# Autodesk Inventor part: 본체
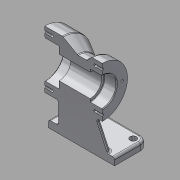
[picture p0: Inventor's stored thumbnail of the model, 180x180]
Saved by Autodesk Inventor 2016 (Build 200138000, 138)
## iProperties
Created: 2019-01
Part Number: 본체
Material: 알루미늄 6061
Document SubType Name: Modeling
Designer: MIRAE
Density: 2.7 g/cm^3
Appearance: 알루미늄 - 평지
Mass: 898.935 g
Surface Area: 600.974 cm^2
Volume: 332.939 cm^3
Author: MIRAE
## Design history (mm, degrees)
sketch "스케치1"
  geometry: L1 (-80, 0)-(0, 0); L2 (0, 0)-(0, 40); L3 (0, 40)-(-25, 40); L4 (-25, 40)-(-45.785, 28); L5 (-45.785, 28)-(-59.126, 28); L6 (-65, 35)-(-80, 35); L7 (-80, 35)-(-80, 0); L8 (-59.126, 28)-(-65, 35); 2 further points
  constraints: 16 end point, 2 parallel, 2 perpendicular, 1 coincident, 1 horizontal, 1 midpoint, 1 vertical
  dimensions: "d0" = 80 diameter of L3 L1; "d1" = 70 diameter of L6 L1; "d2" = 56 diameter of L5 L1; "d3" = 25 distance of L2.end L3.end; "d4" = 80 distance between parallel lines of L7 L2; "d7" = 30 deg angle of L5 L4; "d8" = 50 deg angle of L5 L8; "d9" = 15 distance of L6.start L6.end
revolve "회전1" sketch "스케치1" stored, may be unused: angle "d10" = 90 deg
sketch "스케치2"
  geometry: L1 (-80, -35)-(-80, 35) reference; L2 (-80, 0)-(0, 0); L3 (0, -40)-(0, 40) reference; L4 (0, 0)-(0, 26); L5 (0, 26)-(-20, 26); L6 (-20, 26)-(-20, 16); L7 (-20, 16)-(-63, 16); L8 (-63, 16)-(-63, 20); L9 (-59.126, -28)-(-59.126, 28) reference; L10 (-63, 20)-(-80, 20); L11 (-80, 0)-(-80, 20); 1 further point
  constraints: 16 end point, 3 perpendicular, 2 midpoint, 2 point on line, 1 collinear, 1 horizontal, 1 parallel
  dimensions: "d11" = 52 diameter of L5 L2; "d12" = 40 diameter of L10 L2; "d13" = 32 diameter of L7 L2; "d14" = 20 distance of L4.end L5.end; "d15" = 17 distance of L8.end L10.end
revolve "회전2" sketch "스케치2" stored, may be unused: angle "d16" = 90 deg
node "작업 평면2"
sketch "스케치4"
  geometry: L1 (5, -46)-(97, -46); L2 (97, -46)-(97, 46); L3 (97, 46)-(5, 46); L4 (5, 46)-(5, -46); L5 (5, -46)-(97, 46); L6 (97, -46)-(5, 46); 3 further points
  constraints: 12 end point, 3 midpoint, 2 parallel, 1 horizontal, 1 horizontal alignment, 1 perpendicular
  dimensions: "d19" = 92 distance of L3.end L2.end; "d20" = 92 distance of L2.end L1.end; "d22" = 5 distance from line of L4 point (0, 0)
extrude "돌출1" join sketch "스케치4" distance "d23" = 10; taper "d24" = 0 deg
sketch "스케치6"
  geometry: L1 (97, 46)-(5, 46) reference; L2 (5, 46)-(5, -46) reference; C1 r 16 at (35, 0); 1 further point
  constraints: 1 centre point
  dimensions: "d25" = 46 distance from line of C1.centre L1; "d26" = 30 distance from line of C1.centre L2; "d27" = 32 diameter of C1
extrude "돌출2" join sketch "스케치6" stored distance "d28" = 10; taper "d29" = 0 deg
sketch "스케치7"
  geometry: L1 (-87, -70)-(-71.26, -36.246); L2 (-97, -80)-(-97, -70) reference; L3 (-97, -70)-(-5, -70) reference; 1 further point
  constraints: 2 end point, 1 point on line
  dimensions: "d30" = 10 distance from line of L2 L1.start; "d31" = 25 deg angle of L2 L1
feature "리브1" sketch "스케치7" dims "d32" = 1, "d33" = 10, "d34" = 0, "d35" = 0, "d36" = 1, "d37" = 1
fillet "모깎기1" dims "d38" = 10
hole "구멍1" diameter "d41" = 9; stored, may be unused: countersink angle "d45" = 90 deg, drill point angle "d47" = 118 deg; dims "d39" = 10, "d40" = 10, "d42" = 6, "d43" = 4, "d44" = 2, "d46" = 8
hole "구멍2" diameter "d50" = 9; stored, may be unused: countersink angle "d54" = 90 deg, drill point angle "d56" = 118 deg; dims "d48" = 10, "d49" = 10, "d51" = 6, "d52" = 4, "d53" = 2, "d55" = 8
hole "구멍3" diameter "d59" = 9; stored, may be unused: countersink angle "d63" = 90 deg, drill point angle "d65" = 118 deg; dims "d57" = 10, "d58" = 10, "d60" = 6, "d61" = 4, "d62" = 2, "d64" = 8
hole "구멍4" diameter "d68" = 9; stored, may be unused: countersink angle "d72" = 90 deg, drill point angle "d74" = 118 deg; dims "d66" = 10, "d67" = 10, "d69" = 6, "d70" = 4, "d71" = 2, "d73" = 8
sketch "스케치8"
  geometry: 5 further points
  constraints: 1 horizontal alignment, 5 other
  dimensions: "d75" = 27.5 distance of point (0, 0) point (-27.5, 0); "d78" = 360 deg dimension on point (0, 0) point (-27.5, 0) (derived)
hole "구멍5" sketch "스케치8" at (-27.5, 0), (0, -27.5), (27.5, 0), (0, 27.5) diameter "d80" = 3.242; stored, may be unused: countersink angle "d84" = 90 deg, drill point angle "d86" = 118 deg; dims "d81" = 9, "d82" = 4, "d83" = 2, "d85" = 11
sketch "스케치9"
  geometry: 5 further points
  constraints: 1 horizontal alignment, 5 other
  dimensions: "d87" = 33 distance of point (0, 0) point (33, 0); "d90" = 360 deg dimension on point (0, 0) point (33, 0) (derived)
hole "구멍6" sketch "스케치9" at (33, 0), (0, 33), (-33, 0), (0, -33) diameter "d92" = 3.242; stored, may be unused: countersink angle "d96" = 90 deg, drill point angle "d98" = 118 deg; dims "d93" = 9, "d94" = 4, "d95" = 2, "d97" = 11
fillet "모깎기2" dims "d99" = 3
fillet "모깎기3" dims "d100" = 3
fillet "모깎기4" dims "d101" = 3
chamfer "모따기1" distance "d102" = 1; stored, may be unused: second distance "d103" = 2, angle "d104" = 45 deg
chamfer "모따기2" distance "d105" = 1; stored, may be unused: second distance "d106" = 2, angle "d107" = 45 deg
fillet "모깎기5" dims "d108" = 1
fillet "모깎기6" dims "d109" = 0.6
sketch "스케치10"
  geometry: L1 (-10, 7)-(-10, 0) reference; L2 (82, 0)-(72, 0) reference; 2 further points
  constraints: 1 other
  dimensions: "d110" = 46 distance from line of point (36, 4) L1; "d111" = 4 distance from line of L2 point (36, 4)
feature "엠보싱1" sketch "스케치10" dims "d0" = 80, "d1" = 70, "d2" = 56, "d3" = 25, "d4" = 80, "d7" = 30 deg, "d8" = 50 deg, "d9" = 15, "d12" = 40, "d112" = 0.5, "d113" = 0
feature "분할1"
node "솔리드1"
